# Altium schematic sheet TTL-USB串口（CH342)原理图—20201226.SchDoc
size A4
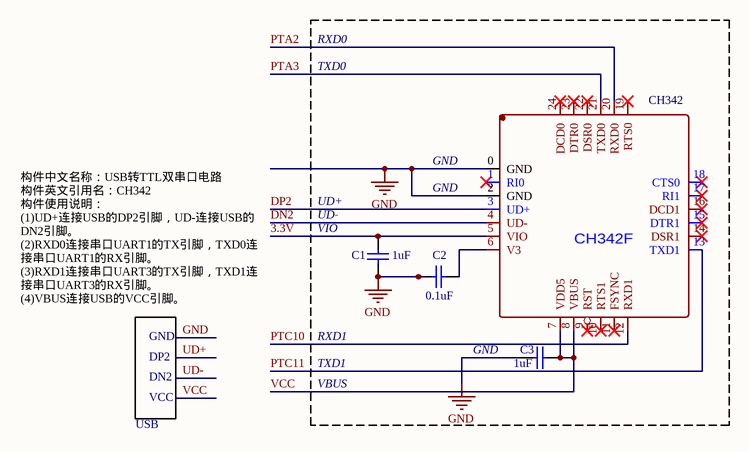
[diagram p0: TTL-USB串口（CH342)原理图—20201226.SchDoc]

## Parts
C1  value 1uF  [0603]  (hidden comment: Cap)
C2  value 0.1uF  [0603]  (hidden comment: Cap)
C3  value 1uF  [0603]  (hidden comment: Cap)
CH342  ch342  [ch342]  (value not drawn)

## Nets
GND: C1.1 C2.1 C3.2 CH342.0(GND) CH342.2(GND)
3.3V: C1.2 CH342.5(VIO)
DN2: CH342.4(UD-)
DP2: CH342.3(UD+)
PTA2: CH342.20(RXD0)
PTA3: CH342.21(TXD0)
PTC10: CH342.12(RXD1)
PTC11: CH342.13(TXD1)
VCC: C3.1 CH342.7(VDD5) CH342.8(VBUS)
NetC2_2: C2.2 CH342.6(V3)

Not connected (* = marked no-connect by the designer): CH342 1(RI0)* 9(RST)* 10(RTS1)* 11(FSYNC)* 14(DSR1)* 15(DTR1)* 16(DCD1)* 17(RI1)* 18(CTS0)* 19(RTS0)* 22(DSR0)* 23(DTR0)* 24(DCD0)*

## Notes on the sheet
- RXD0
- TXD0
- UD+
- (near CH342) GND
- GND
- (near C1) UD-
- (near C1) VIO
- 构件中文名称：USB转TTL双串口电路
  构件英文引用名：CH342
  构件使用说明：
  (1)UD+连接USB的DP2引脚，UD-连接USB的DN2引脚。
  (2)RXD0连接串口UART1的TX引脚，TXD0连接串口UART1的RX引脚。
  (3)RXD1连接串口UART3的TX引脚，TXD1连接串口UART3的RX引脚。
  (4)VBUS连接USB的VCC引脚。
- RXD1
- DP2
- DN2
- VCC
- TXD1
- VBUS
- USB

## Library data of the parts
C1-C3 = Cap: Capacitor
